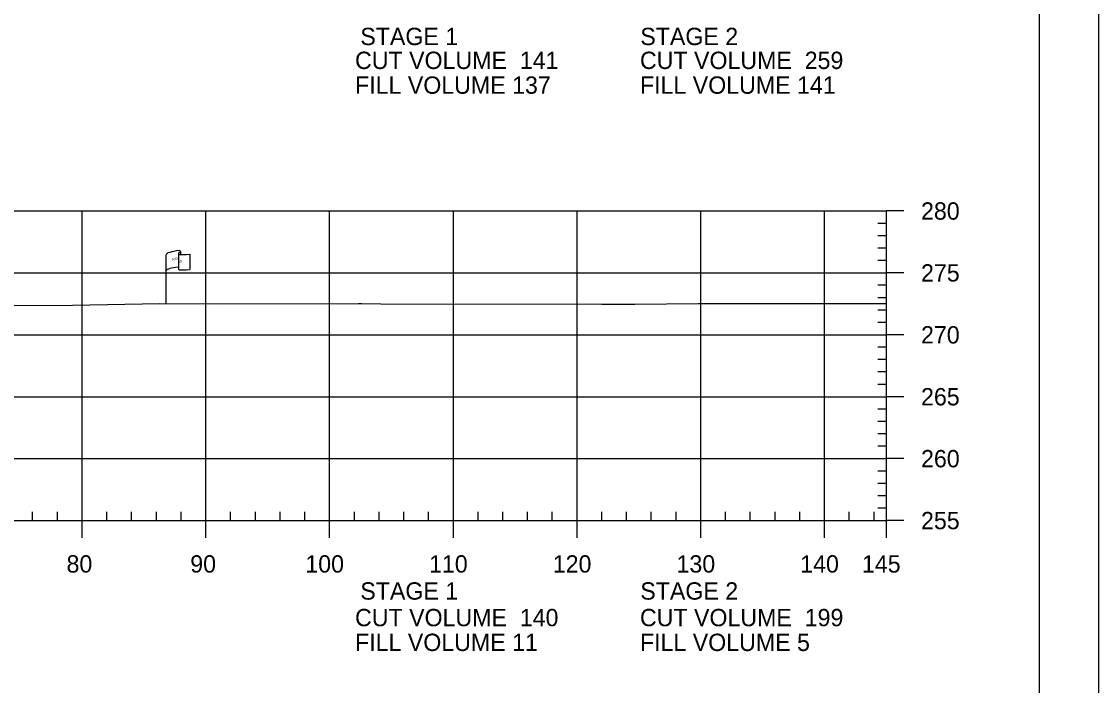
# Model space of a CAD drawing. Extents: x 1365647 to 1367999, y 387113 to 400173.
# Drawn here: x 1365970 to 1366057, y 388972.8 to 389026.4 of the extents above; entities that cross this region are included whole.
import ezdxf

# ---------------------------------------------------------------- set-up
doc = ezdxf.new("R2010")
doc.units = 0
for name, color, linetype in [('E_Existing ROW', 7, 'Continuous'), ('R_Axis', 7, 'Continuous'), ('R_Axis Annot', 7, 'Continuous'), ('R_Border', 7, 'Continuous'), ('R_Exist Surface', 7, 'Continuous'), ('R_Grid', 7, 'Continuous'), ('R_No Plot', 7, 'Continuous')]:
    doc.layers.add(name, color=color, linetype=linetype)

msp = doc.modelspace()

# ---------------------------------------------------------------- linework, layer by layer
at = {"layer": 'E_Existing ROW'}
for p, q in [((1365981.674, 389003.6), (1365981.674, 389007.55)), ((1365982.669, 389007.645), (1365982.669, 389007.631)), ((1365982.669, 389007.631), (1365982.669, 389006.405)), ((1365982.837, 389007.801), (1365982.837, 389007.561)), ((1365983.604, 389007.607), (1365983.604, 389006.367))]:
    msp.add_line(p, q, dxfattribs=at)
for centre, radius, start, end in [((1365982.747, 389007.645), 0.078, 88.6458, 274.28284), ((1365982.758, 389007.801), 0.0783, 263.07118, 93.95638), ((1365982.747, 389006.405), 0.0783, 180, 273.95638)]:
    msp.add_arc(centre, radius, start, end, dxfattribs=at)
for centre, major_axis, ratio, start_param, end_param in [((1365983.256, 389007.594), (-1.582, -0.043), 0.19887, 5.030368, 6.283185), ((1365983.963, 389007.709), (-1.227, -0.134), 0.052933, 0.159456, 1.268315), ((1365983.25, 389006.276), (-1.582, -0.043), 0.19887, 5.083035, 6.194897), ((1365983.963, 389006.469), (-1.227, -0.134), 0.052933, 0.159456, 1.268315)]:
    msp.add_ellipse(centre, major_axis=major_axis, ratio=ratio, start_param=start_param, end_param=end_param, dxfattribs=at)
at = {"layer": 'R_Axis'}
for p, q in [((1366039.888, 388986.083), (1366039.888, 389011.083)), ((1366041.288, 389011.083), (1366039.888, 389011.083)), ((1366039.888, 389010.083), (1366039.188, 389010.083)), ((1366039.888, 389009.083), (1366039.188, 389009.083)), ((1366039.888, 389008.083), (1366039.188, 389008.083)), ((1366039.888, 389007.083), (1366039.188, 389007.083)), ((1366041.288, 389006.083), (1366039.888, 389006.083)), ((1366039.888, 389005.083), (1366039.188, 389005.083)), ((1366039.888, 389004.083), (1366039.188, 389004.083)), ((1366039.888, 389003.083), (1366039.188, 389003.083)), ((1366039.888, 389002.083), (1366039.188, 389002.083)), ((1366041.288, 389001.083), (1366039.888, 389001.083)), ((1366039.888, 389000.083), (1366039.188, 389000.083)), ((1366039.888, 388999.083), (1366039.188, 388999.083)), ((1366039.888, 388998.083), (1366039.188, 388998.083)), ((1366039.888, 388997.083), (1366039.188, 388997.083)), ((1366041.288, 388996.083), (1366039.888, 388996.083)), ((1366039.888, 388995.083), (1366039.188, 388995.083)), ((1366039.888, 388994.083), (1366039.188, 388994.083)), ((1366039.888, 388993.083), (1366039.188, 388993.083)), ((1366039.888, 388992.083), (1366039.188, 388992.083)), ((1366041.288, 388991.083), (1366039.888, 388991.083)), ((1366039.888, 388990.083), (1366039.188, 388990.083)), ((1366039.888, 388989.083), (1366039.188, 388989.083)), ((1366039.888, 388988.083), (1366039.188, 388988.083)), ((1366039.888, 388987.083), (1366039.188, 388987.083)), ((1365970.888, 388986.083), (1365970.888, 388986.783)), ((1365972.888, 388986.083), (1365972.888, 388986.783)), ((1365976.888, 388986.083), (1365976.888, 388986.783)), ((1365978.888, 388986.083), (1365978.888, 388986.783)), ((1365980.888, 388986.083), (1365980.888, 388986.783)), ((1365982.888, 388986.083), (1365982.888, 388986.783)), ((1365986.888, 388986.083), (1365986.888, 388986.783)), ((1365988.888, 388986.083), (1365988.888, 388986.783)), ((1365990.888, 388986.083), (1365990.888, 388986.783)), ((1365992.888, 388986.083), (1365992.888, 388986.783)), ((1365996.888, 388986.083), (1365996.888, 388986.783)), ((1365998.888, 388986.083), (1365998.888, 388986.783)), ((1366000.888, 388986.083), (1366000.888, 388986.783)), ((1366002.888, 388986.083), (1366002.888, 388986.783)), ((1366006.888, 388986.083), (1366006.888, 388986.783)), ((1366008.888, 388986.083), (1366008.888, 388986.783)), ((1366010.888, 388986.083), (1366010.888, 388986.783)), ((1366012.888, 388986.083), (1366012.888, 388986.783)), ((1366016.888, 388986.083), (1366016.888, 388986.783)), ((1366018.888, 388986.083), (1366018.888, 388986.783)), ((1366020.888, 388986.083), (1366020.888, 388986.783)), ((1366022.888, 388986.083), (1366022.888, 388986.783)), ((1366026.888, 388986.083), (1366026.888, 388986.783)), ((1366028.888, 388986.083), (1366028.888, 388986.783)), ((1366030.888, 388986.083), (1366030.888, 388986.783)), ((1366032.888, 388986.083), (1366032.888, 388986.783)), ((1366036.888, 388986.083), (1366036.888, 388986.783)), ((1366038.888, 388986.083), (1366038.888, 388986.783)), ((1365749.888, 388986.083), (1366039.888, 388986.083)), ((1365974.888, 388984.683), (1365974.888, 388986.083)), ((1365984.888, 388984.683), (1365984.888, 388986.083)), ((1365994.888, 388984.683), (1365994.888, 388986.083)), ((1366004.888, 388984.683), (1366004.888, 388986.083)), ((1366014.888, 388984.683), (1366014.888, 388986.083)), ((1366024.888, 388984.683), (1366024.888, 388986.083)), ((1366034.888, 388984.683), (1366034.888, 388986.083)), ((1366039.888, 388984.683), (1366039.888, 388986.083)), ((1366041.288, 388986.083), (1366039.888, 388986.083))]:
    msp.add_line(p, q, dxfattribs=at)
at = {"layer": 'R_Border'}
msp.add_line((1366052.275, 388870.083), (1366052.275, 389075.543), dxfattribs=at)
at = {"layer": 'R_Exist Surface'}
msp.add_lwpolyline([(1365968, 389003.477), (1365971.693, 389003.442), (1365974.103, 389003.479), (1365981.16, 389003.601), (1365986.178, 389003.585), (1365997.228, 389003.604), (1365997.482, 389003.608), (1365999.032, 389003.597), (1366016.896, 389003.571), (1366018.214, 389003.562), (1366019.544, 389003.556), (1366024.679, 389003.605), (1366039.888, 389003.609)], dxfattribs=at)
at = {"layer": 'R_Grid'}
for p, q in [((1365749.888, 389011.083), (1366039.888, 389011.083)), ((1365974.888, 388986.083), (1365974.888, 389011.083)), ((1365984.888, 388986.083), (1365984.888, 389011.083)), ((1365994.888, 388986.083), (1365994.888, 389011.083)), ((1366004.888, 388986.083), (1366004.888, 389011.083)), ((1366014.888, 388986.083), (1366014.888, 389011.083)), ((1366024.888, 388986.083), (1366024.888, 389011.083)), ((1366034.888, 388986.083), (1366034.888, 389011.083)), ((1366039.888, 388986.083), (1366039.888, 389011.083)), ((1365749.888, 389006.083), (1366039.888, 389006.083)), ((1365749.888, 389001.083), (1366039.888, 389001.083)), ((1365749.888, 388996.083), (1366039.888, 388996.083)), ((1365749.888, 388991.083), (1366039.888, 388991.083)), ((1365749.888, 388986.083), (1366039.888, 388986.083))]:
    msp.add_line(p, q, dxfattribs=at)
at = {"layer": 'R_No Plot'}
msp.add_lwpolyline([(1365723.687, 389079.437), (1366057.027, 389079.437), (1366057.027, 388866.1), (1365723.687, 388866.1)], close=True, dxfattribs=at)

# ---------------------------------------------------------------- texts
at = {"layer": 'E_Existing ROW'}
for s, height, rotation, p in [('R ', 0.2, 9.98841, (1365982.193, 389007.052)), (' O', 0.2, 9.98841, (1365982.339, 389007.097)), ('W', 0.2, 351.17882, (1365982.669, 389006.928)), ('DWB 11-9-07', 0.001, 90, (1365982.836, 389007.561)), ('DWB 11-9-07', 0.001, 5.07169, (1365983.594, 389006.367)), ('DWB 11-9-07', 0.001, 90, (1365981.673, 389003.6))]:
    msp.add_text(s, height=height, rotation=rotation, dxfattribs=at).set_placement(p)
at = {"layer": 'R_Axis Annot'}
for s, p in [('STAGE 1', (1365997.371, 389024.478)), ('STAGE 2', (1366020, 389024.478)), ('CUT VOLUME  141', (1365996.946, 389022.549)), ('CUT VOLUME  259', (1366019.972, 389022.549)), ('FILL VOLUME 137', (1365996.946, 389020.549)), ('FILL VOLUME 141', (1366019.972, 389020.549)), ('280', (1366042.688, 389010.383)), ('275', (1366042.688, 389005.383)), ('270', (1366042.688, 389000.383)), ('265', (1366042.688, 388995.383)), ('260', (1366042.688, 388990.383)), ('255', (1366042.688, 388985.383)), ('80', (1365973.627, 388981.883)), ('90', (1365983.627, 388981.883)), ('100', (1365992.927, 388981.883)), ('110', (1366002.927, 388981.883)), ('120', (1366012.927, 388981.883)), ('130', (1366022.927, 388981.883)), ('140', (1366032.927, 388981.883)), ('145', (1366037.914, 388981.883)), ('STAGE 1', (1365997.371, 388979.698)), ('STAGE 2', (1366020, 388979.698)), ('CUT VOLUME  140', (1365996.946, 388977.549)), ('CUT VOLUME  199', (1366019.972, 388977.549)), ('FILL VOLUME 11', (1365996.946, 388975.549)), ('FILL VOLUME 5', (1366019.972, 388975.549))]:
    msp.add_text(s, height=1.4, dxfattribs=at).set_placement(p)

doc.saveas('drawing.dxf')
